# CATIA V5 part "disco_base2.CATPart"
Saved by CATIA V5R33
Part number: disco_base2
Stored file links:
  C:\Users\Ryzen5700u\Desktop\robot_cicloidale_singolo\Assieme_robot_cicloidale_singolo\disco_base2.CATPart

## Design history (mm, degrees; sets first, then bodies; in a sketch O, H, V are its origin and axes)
Body1 "Solido1" (main body)
  Solid1: solid without history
